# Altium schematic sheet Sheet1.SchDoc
size A; SheetNumber: 1; SheetTotal: 1
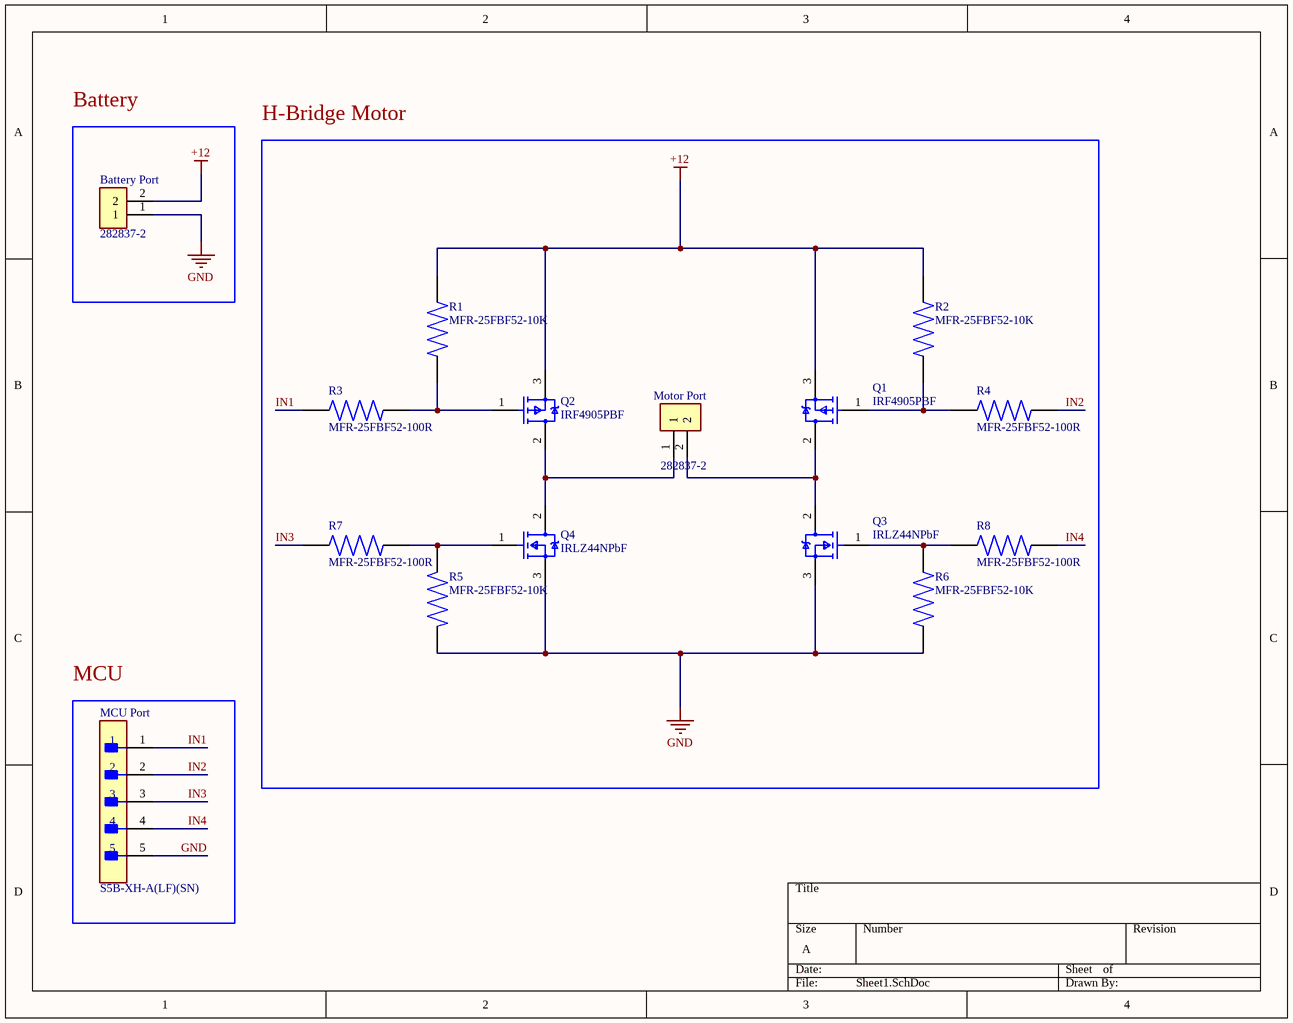
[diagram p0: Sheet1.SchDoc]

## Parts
Battery_Port  282837-2  [TE_282837-2]
MCU_Port  S5B-XH-A(LF)(SN)  [FP-S5B-XH-A_LF_SN-MFG]
Motor_Port  282837-2  [TE_282837-2]
Q1  IRF4905PBF  [FP-PG-TO220-3-MFG]
Q2  IRF4905PBF  [FP-PG-TO220-3-MFG]
Q3  IRLZ44NPbF  [FP-PG-TO220-3-MFG]
Q4  IRLZ44NPbF  [FP-PG-TO220-3-MFG]
R1  MFR-25FBF52-10K  [RESAD1100W55L680D260]
R2  MFR-25FBF52-10K  [RESAD1100W55L680D260]
R3  MFR-25FBF52-100R  [RESAD1100W55L680D260]
R4  MFR-25FBF52-100R  [RESAD1100W55L680D260]
R5  MFR-25FBF52-10K  [RESAD1100W55L680D260]
R6  MFR-25FBF52-10K  [RESAD1100W55L680D260]
R7  MFR-25FBF52-100R  [RESAD1100W55L680D260]
R8  MFR-25FBF52-100R  [RESAD1100W55L680D260]

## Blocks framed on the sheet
Battery: Battery_Port
H-Bridge Motor: Motor_Port Q1-Q4 R1-R8
MCU: MCU_Port

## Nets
+12: Battery_Port.2 Q1.3(SOURCE) Q2.3(SOURCE) R1.2 R2.2
GND: Battery_Port.1 MCU_Port.5 Q3.3(S) Q4.3(S) R5.2 R6.1
IN1: MCU_Port.1 R3.1
IN2: MCU_Port.2 R4.2
IN3: MCU_Port.3 R7.1
IN4: MCU_Port.4 R8.2
NetMotor_Port_1: Motor_Port.1 Q2.2(DRAIN) Q4.2(D)
NetMotor_Port_2: Motor_Port.2 Q1.2(DRAIN) Q3.2(D)
NetQ1_1: Q1.1(GATE) R2.1 R4.1
NetQ2_1: Q2.1(GATE) R1.1 R3.2
NetQ3_1: Q3.1(G) R6.2 R8.1
NetQ4_1: Q4.1(G) R5.1 R7.2

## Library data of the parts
Battery_Port Motor_Port = 282837-2: MF: TE Connectivity
MCU_Port = CMP-17439-000302-1: CONN HEADER R/A 5POS 2.5MM; Contact Resistance: 10mR; Voltage Rating: 250V; Number of Contacts: 5; Current Rating: 3A; Insulation Resistance: 1GR; Wire/Cable Gauge: 22AWG
Q1 Q2 = CMP-32901-000200-1: MOSFET P-CH 55V 74A TO-220AB; Drain to Source Resistance: 20mR; Input Capacitance: 3.4nF; Max Dual Supply Voltage: -55V; Power Dissipation: 200W; Turn-On Delay Time: 18ns; Element Configuration: Single; Threshold Voltage: -4V; Gate to Source Voltage (Vgs): 20V; Turn-Off Delay Time: 61ns
Q3 Q4 = CMP-32901-000488-1: MOSFET N-CH 55V 47A TO220AB; Turn-On Delay Time: 11ns; Gate to Source Voltage (Vgs): 16V; Element Configuration: Single; Rds On Max: 22mR; Turn-Off Delay Time: 26ns; Max Power Dissipation: 110W; Threshold Voltage: 2V; Drain to Source Resistance: 35mR; Input Capacitance: 1.7nF
R1 R2 R5 R6 = MFR-25FBF52-10K: 10.2 kOhms Â±1% 0.25W, 1/4W Through Hole Resistor Axial - Metal Film; MF: Yageo
R3 R4 R7 R8 = MFR-25FBF52-10K: 100 Ohms Â±1% 0.25W, 1/4W Through Hole Resistor Axial - Metal Film; MF: Yageo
